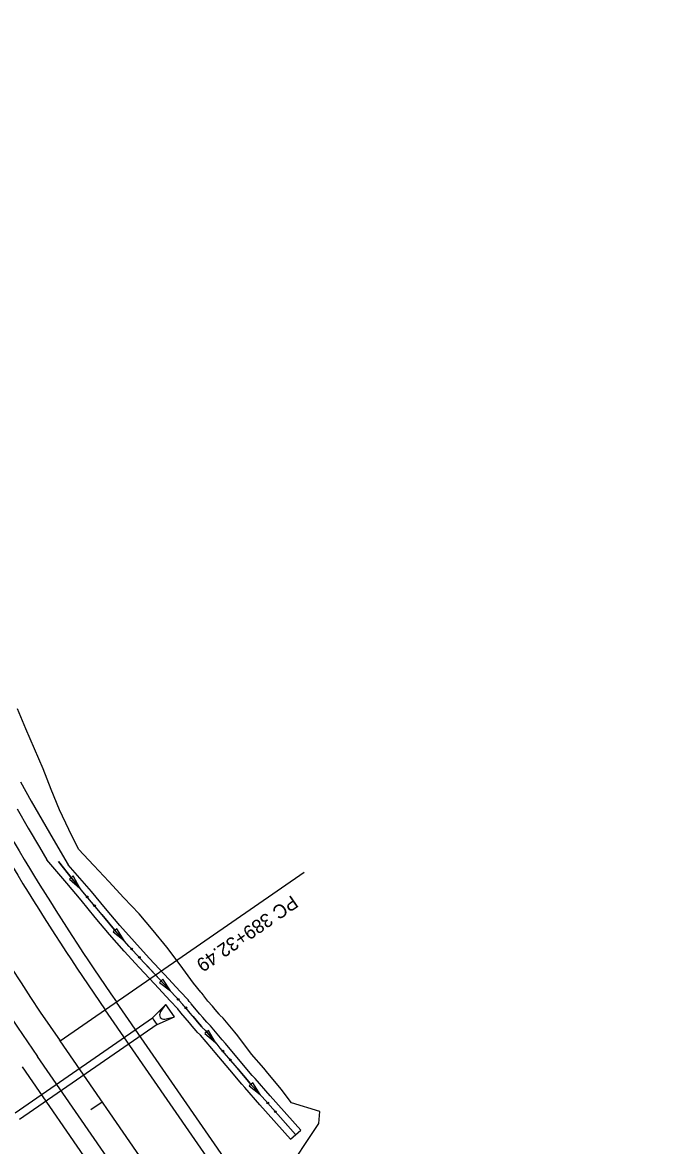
# Model space of a CAD drawing. Extents: x 948761 to 996004, y 1858548 to 1925175.
# Drawn here: x 960301.6 to 960583.8, y 1909705 to 1910197.4 of the extents above; entities that cross this region are included whole.
import ezdxf

# ---------------------------------------------------------------- set-up
doc = ezdxf.new("R2010")
doc.units = 0
for name, color, linetype in [('62', 7, 'Continuous'), ('R_Drainage', 7, 'Continuous'), ('R_Horz Alg', 7, 'Continuous'), ('R_Horz Alg Annot', 7, 'Continuous'), ('R_Proposed Const Limits', 7, 'Continuous'), ('R_Proposed Road', 7, 'Continuous')]:
    doc.layers.add(name, color=color, linetype=linetype)

msp = doc.modelspace()

# ---------------------------------------------------------------- linework, layer by layer
at = {"layer": '62'}
for p, q in [((960323.84, 1909823.18), (960322.2, 1909821.84)), ((960322.2, 1909821.84), (960326.82, 1909817.86)), ((960326.82, 1909817.86), (960323.84, 1909823.18)), ((960342.97, 1909800.07), (960341.38, 1909798.67)), ((960346.14, 1909794.87), (960342.97, 1909800.07)), ((960341.38, 1909798.67), (960346.14, 1909794.87)), ((960363.17, 1909777.88), (960361.62, 1909776.44)), ((960361.62, 1909776.44), (960366.47, 1909772.76)), ((960366.47, 1909772.76), (960363.17, 1909777.88)), ((960383.22, 1909755.47), (960381.6, 1909754.11)), ((960386.27, 1909750.19), (960383.22, 1909755.47)), ((960381.6, 1909754.11), (960386.27, 1909750.19)), ((960402.58, 1909732.54), (960401, 1909731.14)), ((960401, 1909731.14), (960405.76, 1909727.34)), ((960405.76, 1909727.34), (960402.58, 1909732.54)), ((960419.05, 1909707.78), (960423.55, 1909711.76))]:
    msp.add_line(p, q, dxfattribs=at)
for points in [[(960300.75, 1909864.42), (960305.46, 1909856.03), (960310.24, 1909847.68), (960315.1, 1909839.36), (960321.67, 1909828.12)], [(960299.37, 1909852.58), (960304.18, 1909844.18), (960309.05, 1909835.83), (960312.36, 1909830.18)], [(960419.05, 1909707.78), (960405.71, 1909722.87), (960399.04, 1909730.42), (960397.79, 1909731.83), (960392.49, 1909738.13), (960386.02, 1909745.82), (960384.62, 1909747.49), (960379.68, 1909753.37), (960378.24, 1909754.71), (960377.89, 1909755.12), (960377.77, 1909755.26), (960376.07, 1909757.29), (960374.84, 1909758.74), (960371.04, 1909763.23), (960370.78, 1909763.54), (960370.05, 1909764.42), (960369.68, 1909764.87), (960366.32, 1909768.5), (960359.46, 1909775.92), (960352.8, 1909783.1), (960346.21, 1909790.26), (960339.75, 1909797.58), (960333.48, 1909805.03), (960327.3, 1909812.53), (960321.14, 1909820.06), (960312.36, 1909830.18)], [(960421.3, 1909709.77), (960414.63, 1909717.31), (960407.96, 1909724.86), (960401.29, 1909732.4), (960400.07, 1909733.79), (960394.78, 1909740.06), (960388.32, 1909747.75), (960386.92, 1909749.42), (960381.86, 1909755.45), (960380.41, 1909756.78), (960380.19, 1909757.05), (960380.07, 1909757.2), (960378.36, 1909759.23), (960377.13, 1909760.68), (960375.18, 1909762.98), (960373.33, 1909765.17), (960373.08, 1909765.47), (960372.38, 1909766.31), (960371.96, 1909766.83), (960368.53, 1909770.54), (960361.66, 1909777.96), (960355.01, 1909785.13), (960348.44, 1909792.27), (960342.02, 1909799.54), (960335.79, 1909806.95), (960329.62, 1909814.43), (960323.47, 1909821.95), (960317.38, 1909829.52)], [(960317.38, 1909829.52), (960323.47, 1909821.95), (960326.82, 1909817.86)], [(960423.55, 1909711.76), (960410.21, 1909726.85), (960403.53, 1909734.39), (960402.34, 1909735.74), (960397.08, 1909742), (960390.62, 1909749.68), (960389.21, 1909751.35), (960384.04, 1909757.52), (960382.59, 1909758.86), (960382.48, 1909758.98), (960382.36, 1909759.13), (960380.65, 1909761.16), (960379.42, 1909762.62), (960375.62, 1909767.11), (960375.38, 1909767.39), (960374.7, 1909768.21), (960374.23, 1909768.8), (960370.73, 1909772.58), (960363.86, 1909779.99), (960357.21, 1909787.17), (960350.67, 1909794.28), (960344.29, 1909801.5), (960338.09, 1909808.87), (960331.94, 1909816.34), (960321.67, 1909828.12)], [(960336.35, 1909806.28), (960336.37, 1909806.25)], [(960336.37, 1909806.25), (960342.02, 1909799.54), (960346.14, 1909794.87)], [(960356.25, 1909783.79), (960356.28, 1909783.76)], [(960356.28, 1909783.76), (960361.66, 1909777.96), (960366.47, 1909772.76)], [(960376.41, 1909761.53), (960376.43, 1909761.5)], [(960376.43, 1909761.5), (960377.13, 1909760.68), (960378.36, 1909759.23), (960380.07, 1909757.2), (960380.19, 1909757.05), (960380.41, 1909756.78), (960381.86, 1909755.45), (960386.27, 1909750.19)], [(960395.92, 1909738.71), (960395.95, 1909738.68)], [(960395.95, 1909738.68), (960400.07, 1909733.79), (960401.29, 1909732.4), (960405.76, 1909727.34)], [(960415.7, 1909716.11), (960415.73, 1909716.08)], [(960415.73, 1909716.08), (960421.3, 1909709.77)]]:
    msp.add_lwpolyline(points, dxfattribs=at)
for centre in [(960330.01, 1909814.01), (960333.2, 1909810.14), (960349.51, 1909791.17), (960352.9, 1909787.48), (960369.9, 1909769.11), (960373.22, 1909765.36), (960389.52, 1909746.38), (960392.74, 1909742.55), (960409.11, 1909723.62), (960412.43, 1909719.86)]:
    msp.add_circle(centre, 0.375, dxfattribs=at)
at = {"layer": 'R_Drainage'}
for p, q in [((960358.62, 1909760.97), (960364.49, 1909766.84)), ((960362.01, 1909763.27), (960364.49, 1909766.84)), ((960368.19, 1909761.49), (960364.49, 1909766.84)), ((960298.4, 1909719.34), (960358.62, 1909760.97)), ((960360.61, 1909758.09), (960358.62, 1909760.97)), ((960360.61, 1909758.09), (960368.19, 1909761.49)), ((960363.96, 1909760.45), (960368.19, 1909761.49)), ((960360.61, 1909758.09), (960300.39, 1909716.46))]:
    msp.add_line(p, q, dxfattribs=at)
msp.add_arc((960363.53, 1909762.23), 1.83, 145.3114, 283.9331, dxfattribs=at)
at = {"layer": 'R_Horz Alg'}
msp.add_line((960559.17, 1909402.06), (960318.1, 1909750.87), dxfattribs=at)
msp.add_arc((961310.39, 1910436.68), 1206.23, 191.44192, 214.64982, dxfattribs=at)
at = {"layer": 'R_Horz Alg Annot'}
for points in [[(960318.1, 1909750.87), (960425.04, 1909824.78)], [(960331.63, 1909720.73), (960336.57, 1909724.14)]]:
    msp.add_lwpolyline(points, dxfattribs=at)
at = {"layer": 'R_Proposed Const Limits'}
for points in [[(960326.25, 1909834.95), (960321.9, 1909843.49), (960317.85, 1909852.2), (960314.23, 1909861.13), (960310.68, 1909870.08), (960306.98, 1909878.93), (960303.18, 1909887.69), (960299.49, 1909896.5)], [(960432, 1909719.86), (960419.59, 1909723.71), (960414.95, 1909729.69), (960408.63, 1909737.48), (960407.39, 1909738.85), (960402.04, 1909745.08), (960396.01, 1909753.07), (960394.65, 1909754.76), (960389.6, 1909760.8), (960388.17, 1909762.14), (960387.94, 1909762.41), (960387.82, 1909762.55), (960386.11, 1909764.58), (960384.88, 1909766.04), (960382.93, 1909768.34), (960381.13, 1909770.56), (960380.9, 1909770.87), (960380.25, 1909771.75), (960379.86, 1909772.29), (960376.6, 1909776.12), (960370.76, 1909784.25), (960364.97, 1909791.93), (960358.9, 1909799.28), (960352.72, 1909806.58), (960346.03, 1909813.57), (960339.48, 1909820.69), (960332.94, 1909827.84), (960326.25, 1909834.95)], [(960496.47, 1909567.22), (960488.78, 1909586.22), (960485.09, 1909595.83), (960480.74, 1909604.98), (960480.53, 1909605.41), (960480.53, 1909605.42), (960480.49, 1909605.4), (960476.44, 1909614.17), (960472.13, 1909623.34), (960468.15, 1909632.75), (960464.65, 1909640.44), (960463.83, 1909641.91), (960459.81, 1909647.21), (960458.41, 1909650.32), (960452.48, 1909658.39), (960445.66, 1909665.82), (960438.97, 1909673.36), (960432.25, 1909680.87), (960430.39, 1909682.98), (960425.82, 1909688.58), (960419.17, 1909696.14), (960425.33, 1909705.37), (960431.49, 1909714.6), (960432, 1909719.86)]]:
    msp.add_lwpolyline(points, dxfattribs=at)
at = {"layer": 'R_Proposed Road'}
for p, q in [((960583.85, 1909419.12), (960342.78, 1909767.92)), ((960578.91, 1909415.71), (960337.84, 1909764.51)), ((960549.3, 1909395.24), (960308.22, 1909744.04)), ((960542.71, 1909390.69), (960301.64, 1909739.5))]:
    msp.add_line(p, q, dxfattribs=at)
for radius, start in [(1218.23, 191.44192), (1182.23, 207.82961), (1176.23, 207.82961)]:
    msp.add_arc((961310.39, 1910436.68), radius, start, 214.64982, dxfattribs=at)

# ---------------------------------------------------------------- texts
at = {"layer": 'R_Horz Alg'}
msp.add_text('+', height=1, rotation=124.6498, dxfattribs=at).set_placement((960318.51, 1909751.15))
at = {"layer": 'R_Horz Alg Annot'}
msp.add_text('PC 389+32.49', height=6, rotation=214.6498, dxfattribs=at).set_placement((960419.66, 1909814.98))

doc.saveas('drawing.dxf')
